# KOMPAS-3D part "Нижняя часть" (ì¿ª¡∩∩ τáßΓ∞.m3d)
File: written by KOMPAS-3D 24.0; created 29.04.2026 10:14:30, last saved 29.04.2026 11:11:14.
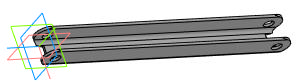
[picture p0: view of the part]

Document properties: Автор: USG_411; Полное имя файла: C:\Users\USG_411\Desktop\ИА-2904_411-12\Нижняя часть.m3d

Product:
- Part/product: Нижняя часть
    Масса: 0.552379

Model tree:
1. Эскиз:1
2. Элемент выдавливания:1
     Расстояние 2 = 298
3. Эскиз:2  (with: Грань.Элемент выдавливания:1, Ребро.Элемент выдавливания:1)
4. Элемент выдавливания:2
     Расстояние 2 = 30
5. Эскиз:3  (with: Грань.Элемент выдавливания:1, Ребро.Элемент выдавливания:1)
6. Элемент выдавливания:3
     Расстояние 2 = 10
